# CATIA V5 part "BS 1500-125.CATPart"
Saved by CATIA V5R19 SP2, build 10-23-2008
Part number: BS 1500-125
Bounding box of the stored display mesh (mm): x -31.459 to 31.459, y -31.459 to 31.459, z 0 to 294
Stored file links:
  C:\Users\Bora\Desktop\3D Katı model\BS serisi\BS 1500\BS 1500-125.CATPart
  C:\Program Files\Dassault Systemes\B19\intel_a\reffiles\standard\MetricThickPitch.txt
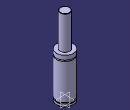
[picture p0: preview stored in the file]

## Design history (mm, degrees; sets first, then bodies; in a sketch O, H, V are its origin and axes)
Body1 (main body)
  Sketch1 on yz-plane, origin (0, 0, 0), H (0, 1, 0), V (0, 0, 1)
    point P1 (31.5, 152)
    point P2 (31.5, 148)
    point P3 (31.5, 152)
    point P7 (18, 293)
    point P9 (18, 293)
    point P14 (31.5, 148)
    arc A1 centre (31.5, 150) radius 2 from (31.5, 152) to (31.5, 148) ccw
    line L1 (31.5, 152) -> (31.5, 168)
    line L2 (31.5, 0) -> (31.5, 8)
    arc A2 centre (17, 293) radius 1 from (18, 293) to (17, 294) ccw
    line L3 (18, 293) -> (18, 168)
    line L4 (29, 13) -> (29, 8)
    line L5 (31.5, 13) -> (31.5, 148)
    line L6 (17, 294) -> (0, 294)
    point P15 (0, 294)
    line L7 (18, 168) -> (31.5, 168)
    line L8 (0, 0) -> (31.5, 0)
    line L9 (29, 13) -> (31.5, 13)
    line L10 (29, 8) -> (31.5, 8)
    coincidence: P15 V, P1 P3, P2 P14, P7 P9
    tangency: L6 A2
    horizontal: L7 H, L8 H, L9 H, L10 H
  Shaft1: profile Sketch1, axis Sketch1.V, angle 360
  Sketch2 on face of Shaft1 from Sketch1.L8, origin (0, 0, 0), H (1, 0, 0), V (0, -1, 0)
    point P1 (10, 0)
    distance P1 V = 10
  Hole1: placed by Sketch2, at (10, 0, 0) direction (0, 0, 1), diameter 6.647, depth 5, threaded "M8", thread diameter 8, thread depth 5, pitch 1.25
  CircPattern1: of Hole1, instances 2, angular step 180, axis from xy-plane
